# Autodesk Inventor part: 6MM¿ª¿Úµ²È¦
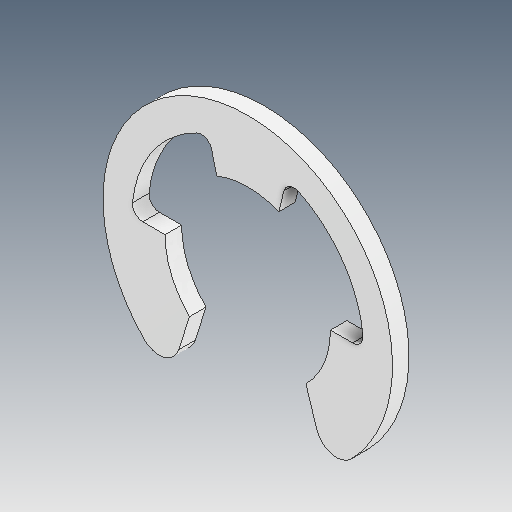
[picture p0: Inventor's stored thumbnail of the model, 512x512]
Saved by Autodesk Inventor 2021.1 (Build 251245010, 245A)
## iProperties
Created: 2021-06
Part Number: 6MM¿ª¿Úµ²È¦
Material: Ogólny
Document SubType Name: Modeling
Designer: user
Density: 1 g/cm^3
Appearance: Domyślna
Author: user
Revision Number: ÈÎºÎ
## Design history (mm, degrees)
feature "ÊäÈë1"
node "Bryła1"
